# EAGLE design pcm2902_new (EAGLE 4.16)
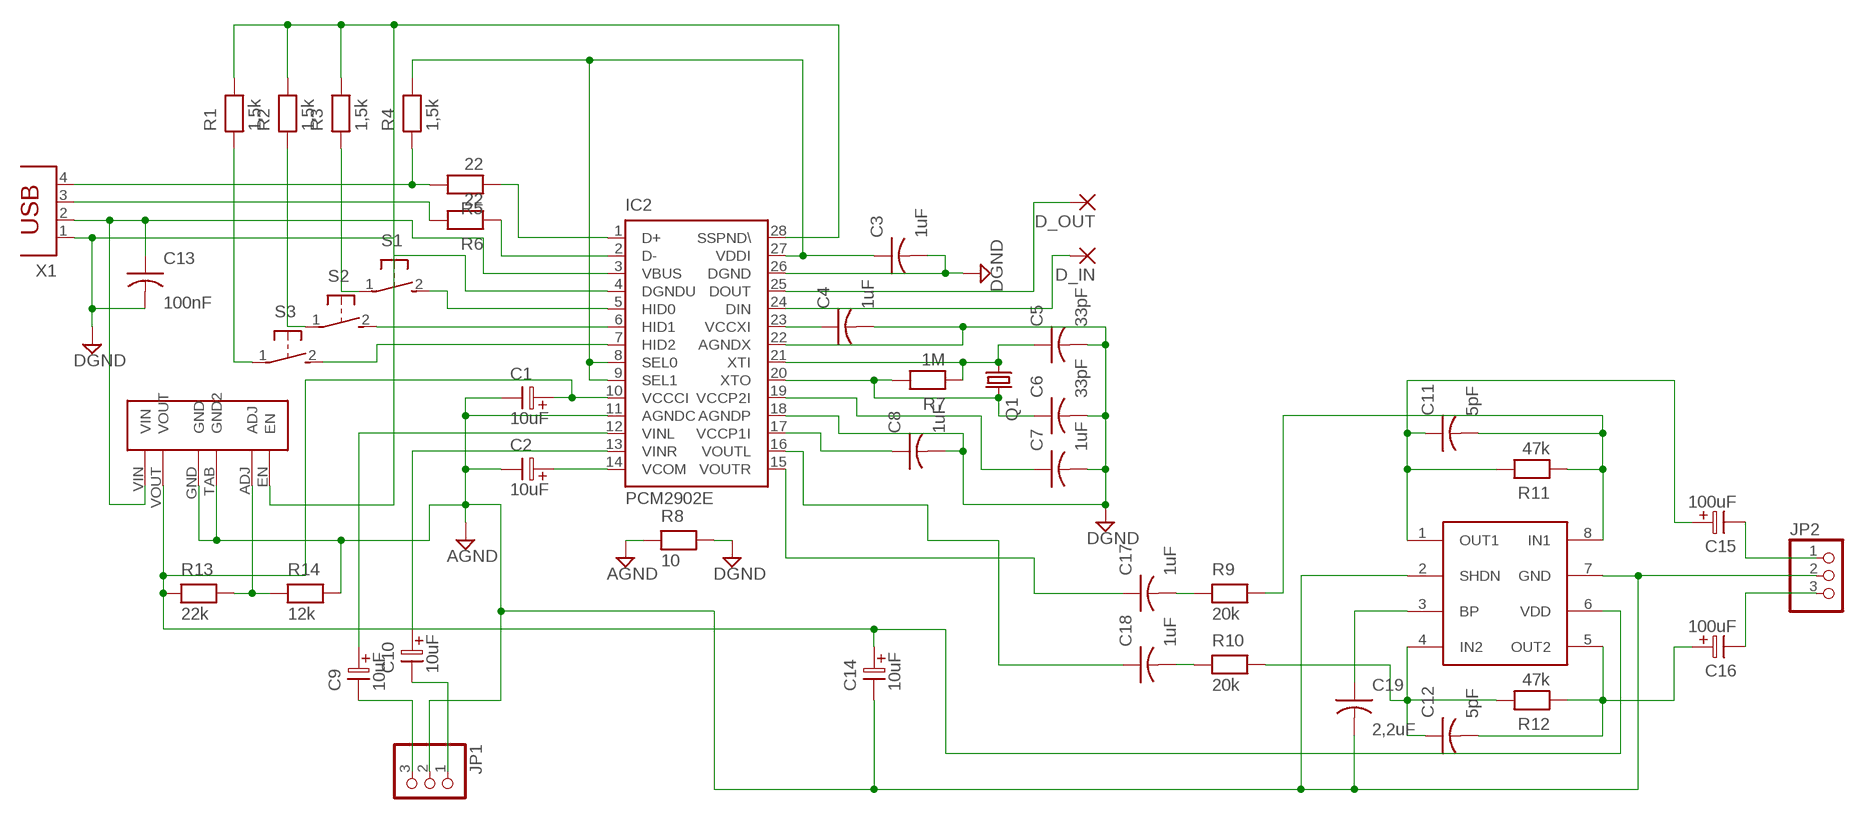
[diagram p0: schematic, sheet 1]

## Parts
C1  10uF  ELC-2,5L  [ES-2,5L]
C2  10uF  ELC-2,5L  [ES-2,5L]
C3  1uF  CAP-5  [C-5]
C4  1uF  CAP-5  [C-5]
C5  33pF  CAP-5  [C-5]
C6  33pF  CAP-5  [C-5]
C7  1uF  CAP-5  [C-5]
C8  1uF  CAP-5  [C-5]
C9  10uF  ELC-2,5L  [ES-2,5L]
C10  10uF  ELC-2,5L  [ES-2,5L]
C11  5pF  CAP-5  [C-5]
C12  5pF  CAP-5  [C-5]
C13  100nF  CAP-2,5  [C-2,5]
C14  10uF  ELC-2,5L  [ES-2,5L]
C15  100uF  ELC-2,5L  [ES-2,5L]
C16  100uF  ELC-2,5L  [ES-2,5L]
C17  1uF  CAP-5  [C-5]
C18  1uF  CAP-5  [C-5]
C19  2,2uF  CAP-5  [C-5]
D_IN  1,6/0,8  [1,6/0,8]
D_OUT  1,6/0,8  [1,6/0,8]
IC2  PCM2902E  [SSOP28DB]
JP1  PINHD-1X3  [1X03]
JP2  PINHD-1X3  [1X03]
Q1  CRYTALHC49S  [HC49/S]
R1  1,5k  RESEU-5  [R-5]
R2  1,5k  RESEU-5  [R-5]
R3  1,5k  RESEU-5  [R-5]
R4  1,5k  RESEU-5  [R-5]
R5  22  RESEU-5  [R-5]
R6  22  RESEU-5  [R-5]
R7  1M  RESEU-5  [R-5]
R8  10  RESEU-5  [R-5]
R9  20k  RESEU-5  [R-5]
R10  20k  RESEU-5  [R-5]
R11  47k  RESEU-5  [R-5]
R12  47k  RESEU-5  [R-5]
R13  22k  RESEU-5  [R-5]
R14  12k  RESEU-5  [R-5]
S1  31-XX  [B3F-31XX]
S2  31-XX  [B3F-31XX]
S3  31-XX  [B3F-31XX]
U$1  TPA302  [SOP8]
U$2  REG102GA-A  [SOT223-5]
X1  PN87520  [PN87520]

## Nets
AGND: C1.2 C2.2 C14.2 C19.2 IC2.11(AGNDC) JP1.2 JP2.2 R8.1 R14.2 U$1.2(SHDN) U$1.7(GND) U$2.GND U$2.TAB(GND2)
DGND: C3.2 C4.2 C5.2 C6.2 C7.2 C8.2 C13.2 IC2.4(DGNDU) IC2.18(AGNDP) IC2.22(AGNDX) IC2.26(DGND) R8.2 X1.1
N$1: C2.1 IC2.14(VCOM)
N$2: C1.1 C14.1 IC2.10(VCCCI) R13.1 U$1.6(VDD) U$2.VOUT
N$3: IC2.1(D+) R5.1
N$4: R4.1 R5.2 X1.4
N$5: R6.2 X1.3
N$6: IC2.2(D-) R6.1
N$7: IC2.6(HID1) S2.2(S)
N$8: C3.1 IC2.8(SEL0) IC2.9(SEL1) IC2.27(VDDI) R4.2
N$9: IC2.7(HID2) S3.2(S)
N$10: IC2.5(HID0) S1.2(S)
N$11: R1.1 S3.1(P)
N$12: R2.1 S2.1(P)
N$13: R3.1 S1.1(P)
N$14: C4.1 IC2.23(VCCXI)
N$15: IC2.28(SSPND\) R1.2 R2.2 R3.2 U$2.EN
N$16: C9.1 IC2.12(VINL)
N$17: C10.1 IC2.13(VINR)
N$18: C5.1 IC2.21(XTI) Q1.1 R7.1
N$19: C6.1 IC2.20(XTO) Q1.2 R7.2
N$20: C7.1 IC2.19(VCCP2I)
N$21: C8.1 IC2.17(VCCP1I)
N$22: D_OUT.1(P) IC2.25(DOUT)
N$23: D_IN.1(P) IC2.24(DIN)
N$24: C18.1 IC2.16(VOUTL)
N$25: C17.1 IC2.15(VOUTR)
N$26: R13.2 R14.1 U$2.ADJ
N$27: C9.2 JP1.3
N$28: C10.2 JP1.1
N$29: C19.1 U$1.3(BP)
N$30: C13.1 IC2.3(VBUS) U$2.VIN X1.2
N$32: C17.2 R9.1
N$33: C18.2 R10.1
N$34: C12.2 C16.1 R12.1 U$1.5(OUT2)
N$35: C12.1 R10.2 R12.2 U$1.4(IN2)
N$36: C11.1 C15.1 R11.2 U$1.1(OUT1)
N$37: C11.2 R9.2 R11.1 U$1.8(IN1)
N$39: C15.2 JP2.1
N$40: C16.2 JP2.3

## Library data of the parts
C1 C2 C9 C10 C14-C16 = discrete:ELC-2,5L
C3-C8 C11 C12 C17-C19 = discrete:CAP-5
C13 = discrete:CAP-2,5
D_IN D_OUT = wirepad:1,6/0,8: THROUGH-HOLE PAD
IC2 = texas:PCM290*: STEREO AUDIO CODEC WITH USB INTERFACE SINGLE-ENDED ANALOG INPUT/OUTPUT AND S/PDIF
JP1 JP2 = pinhead:PINHD-1X3: PIN HEADER
Q1 = crystal:CRYTAL: CRYSTAL
R1-R14 = discrete:RESEU-5
S1-S3 = switch-omron:31-XX: OMRON SWITCH
U$1 = tpa302:TPA302
U$2 = Reg102:REG102GA-A
X1 = con-berg:PN87520: BERG USB connector

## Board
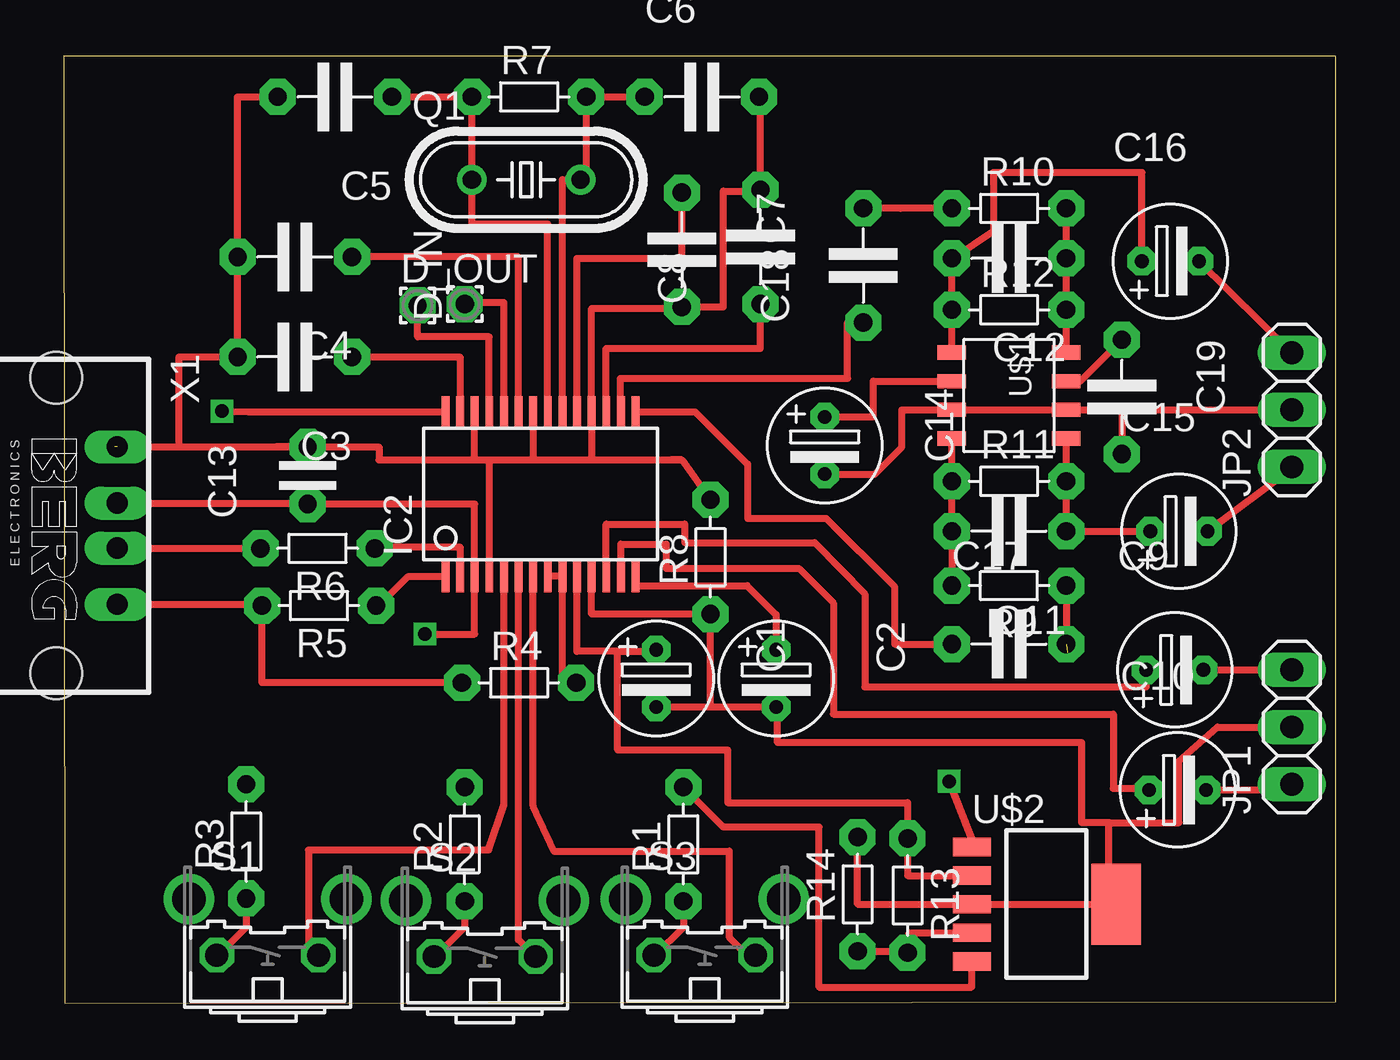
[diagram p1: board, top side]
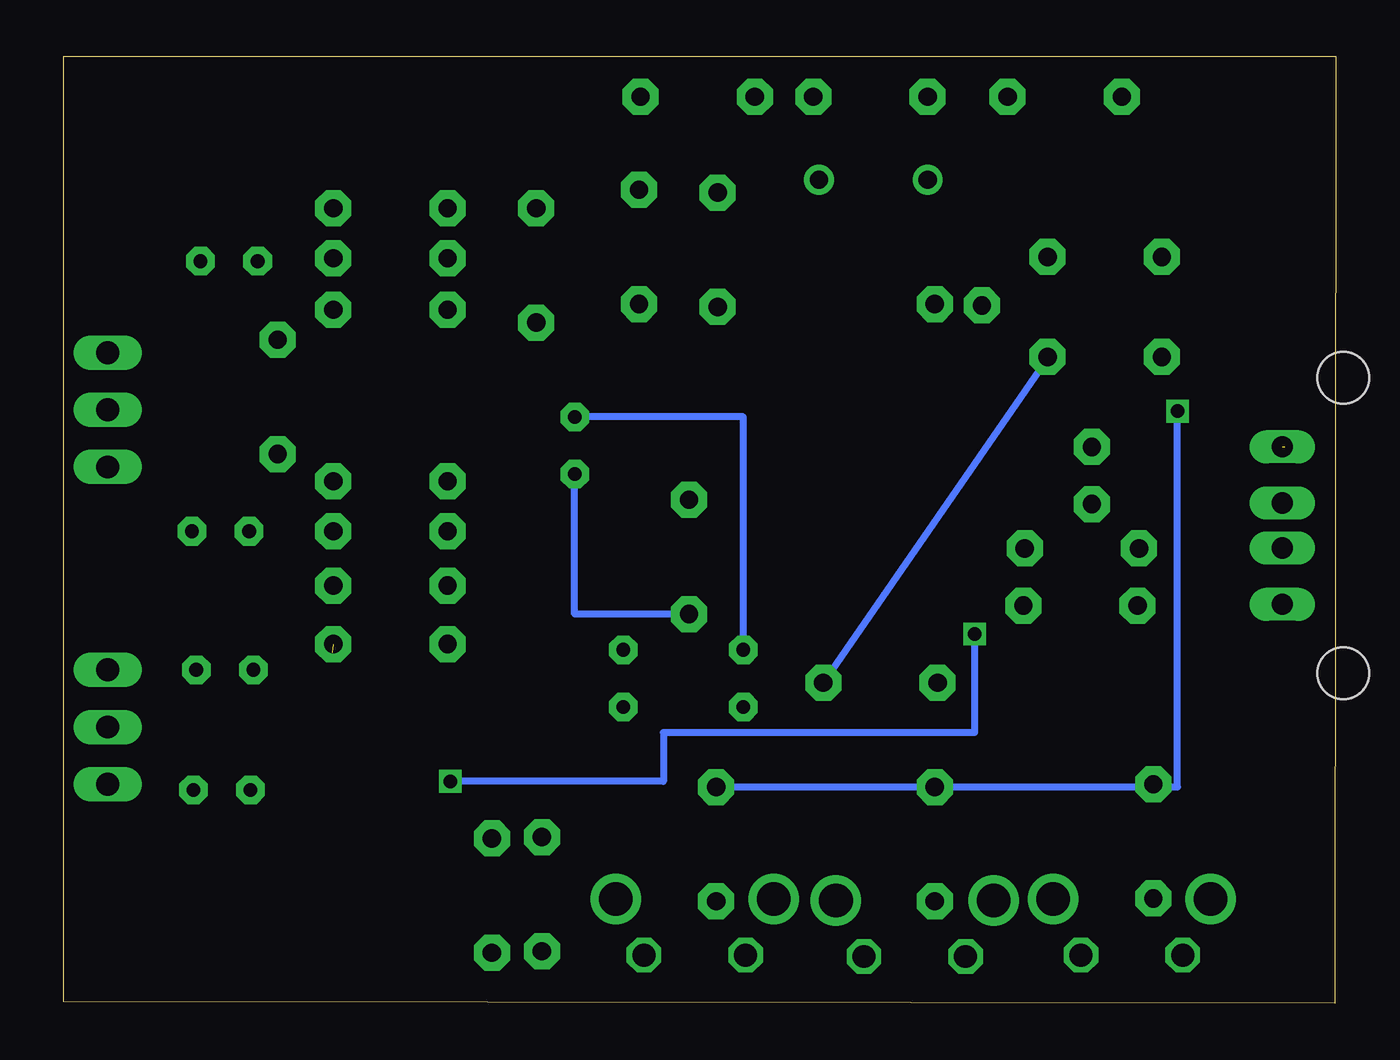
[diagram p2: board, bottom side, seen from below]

Size 56.56 x 42.09 mm. Coordinates in mm from the lower left corner, seen from the top.
Outline: 0.06,0 56.56,0.06 56.56,42.09 0,42.09 0.06,0
Copper layers (1*16): Top 0.035mm / dielectric 1.5mm / Bottom 0.035mm
Design rules "default": minimum track width 10mil, minimum drill 24mil, track to track 8mil, track to pad 8mil, pad to pad 8mil, via to via 8mil, smd to smd 8mil, copper to edge 40mil, drill to drill 8mil, minimum pad ring 10mil, minimum via ring 8mil, stop-mask expansion 4mil, vias tented up to drill 0mil, thermal gap 10mil

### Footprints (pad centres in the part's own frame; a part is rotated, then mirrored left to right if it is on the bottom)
ES-2,5L = drill 0.61 pad 1.27 octagon: 1 0,0; 2 2.54,0
C-5 = drill 0.813 pad 1.6 octagon: 1 -2.54,0; 2 2.54,0
C-2,5 = drill 0.813 pad 1.6 octagon: 1 -1.27,0; 2 1.27,0
1,6/0,8 = drill 0.813 pad 1.6 octagon: 1 0,0
SSOP28DB = smd 0.348 x 1.397: 1 -4.225,-3.656; 2 -3.575,-3.656; 3 -2.925,-3.656; 4 -2.275,-3.656; 5 -1.625,-3.656; 6 -0.975,-3.656; 7 -0.325,-3.656; 8 0.325,-3.656; 9 0.975,-3.656; 10 1.625,-3.656; 11 2.275,-3.656; 12 2.925,-3.656; 13 3.575,-3.656; 14 4.225,-3.656; 15 4.225,3.656; 16 3.575,3.656; 17 2.925,3.656; 18 2.275,3.656; 19 1.625,3.656; 20 0.975,3.656; 21 0.325,3.656; 22 -0.325,3.656; 23 -0.975,3.656; 24 -1.625,3.656; 25 -2.275,3.656; 26 -2.925,3.656; 27 -3.575,3.656; 28 -4.225,3.656
1X03 = drill 1.016 long: 1 -2.54,0; 2 0,0; 3 2.54,0
HC49/S = drill 0.813 round: 1 -2.413,0; 2 2.413,0
R-5 = drill 0.813 pad 1.6 octagon: 1 -2.54,0; 2 2.54,0
B3F-31XX = drill 1.016 octagon: 1 -2.261,-1.245; 2 2.261,-1.245 | drill 1.499 pad 2.159 round: 3 -3.505,1.245; 4 3.505,1.245
SOP8 = smd 0.635 x 1.27: 1 -1.905,-2.54; 2 -0.635,-2.54; 3 0.635,-2.54; 4 1.905,-2.54; 5 1.905,2.54; 6 0.635,2.54; 7 -0.635,2.54; 8 -1.905,2.54
SOT223-5 = smd 0.813 x 1.676: ADJ 1.27,-3.302; EN 2.54,-3.302; GND 0,-3.302; VIN -2.54,-3.302; VOUT -1.27,-3.302 | smd 3.6 x 2.2: TAB 0,3.099
PN87520 = drill 0.95 long: 1 -3.5,2.71; 2 -1,2.71; 3 1,2.71; 4 3.5,2.71 | hole 2.3: -6.57,0; 6.57,0

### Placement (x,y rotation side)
C1  26.35,15.71 270 top
C2  31.68,15.71 270 top
C3  10.28,28.73 180 top
C4  10.28,33.17 180 top
C5  12.06,40.28 180 top
C6  28.38,40.28 0 top
C7  27.49,33.49 270 top
C8  30.98,33.62 90 top
C9  48.13,14.82 0 top
C10  48.25,9.49 0 top
C11  42.03,20.98 180 top
C12  42.03,33.11 180 top
C13  10.85,23.46 90 top
C14  33.84,26.06 270 top
C15  48.32,20.98 0 top
C16  47.94,32.98 0 top
C17  42.03,15.96 0 top
C18  35.56,32.79 90 top
C19  47.05,26.95 270 top
D_IN  17.84,31.08 90 top
D_OUT  15.74,31.01 0 top
IC2  21.2,22.63 0 top
JP1  54.61,12.28 90 top
JP2  54.61,26.38 90 top
Q1  20.57,36.6 0 top
R1  27.55,7.07 90 top
R2  17.84,7.07 90 top
R3  8.12,7.2 90 top
R4  20.25,14.25 0 top
R5  11.36,17.68 180 top
R6  11.3,20.22 180 top
R7  20.7,40.28 0 top
R8  28.76,19.84 90 top
R9  42.03,18.57 180 top
R10  42.03,35.33 0 top
R11  42.03,23.2 0 top
R12  42.03,30.82 0 top
R13  37.52,4.79 270 top
R14  35.3,4.85 90 top
S1  9.08,3.39 0 top
S2  18.73,3.33 0 top
S3  28.51,3.39 0 top
U$1  42.03,27.01 90 top
U$2  43.68,4.41 270 top
X1  -0.32,21.23 270 top

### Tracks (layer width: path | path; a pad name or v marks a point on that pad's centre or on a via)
AGND
  Top 0.305: 28.76,13.17 C1.2 | 28.76,13.17 C2.2 31.75,13.17 31.75,11.58 45.27,11.58 45.27,8.03 46.48,8.03 | IC2.11 23.48,17.3 R8.1 28.76,17.11 | 28.76,13.17 28.76,17.11 | 28.76,17.11 28.7,17.11 | JP1.2 51.3,12.28 49.59,10.76 49.59,8.03 46.48,8.03 | 47.05,26.38 U$1.2 U$1.7 37.27,26.38 37.27,24.71 36.08,23.52 C14.2 | 47.05,26.38 C19.2 | 47.05,26.38 JP2.2 | 46.8,4.41 U$2.TAB 46.48,4.41 | 40.57,4.41 46.48,4.41 | 46.48,4.41 46.48,8.03 | 40.57,4.41 U$2.GND | R14.2 35.3,4.41 40.57,4.41
  Bottom 0.305: 28.63,17.3 R8.1 33.84,17.3 C14.2
DGND  (1 unrouted)
  Top 0.305: 20.89,26.28 IC2.22 20.89,26.29 20.89,24.16 | 27.49,24.16 R8.2 | 18.28,24.16 14.03,24.16 14.03,24.73 C13.2 | 18.28,24.16 18.92,24.16 | 18.92,24.16 20.89,24.16 | 20.89,24.16 23.49,24.16 | 23.49,24.16 27.49,24.16 | 27.49,24.16 26.98,24.16 | 2.28,24.73 5.14,24.73 | 5.14,24.73 C13.2 | IC2.26 18.28,24.16 | 23.49,24.16 23.49,26.29 IC2.18 23.48,30.89 27.49,30.89 C7.2 29.33,30.95 29.33,36.09 30.86,36.09 C8.2 30.98,40.09 C6.2 | 5.14,24.73 5.14,28.73 C3.2 C4.2 7.74,40.28 C5.2 | C13.2 9.46,24.73 | IC2.4 18.93,19 18.92,19.01 18.92,24.16
N$1
  Top 0.305: 25.46,19.01 25.46,18.98 IC2.14 25.43,18.57 30.39,18.57 31.68,17.27 C2.1
N$2
  Top 0.305: C1.1 26.35,15.65 24.63,15.65 | IC2.10 22.83,15.65 24.63,15.65 | U$1.6 36,27.65 36,26.06 33.78,26.06 | C14.1 33.78,26.06 | 33.78,26.06 33.78,26.12 | U$2.VOUT 37.52,5.68 R13.1 37.52,8.92 29.52,8.92 29.52,11.26 24.63,11.26 24.63,15.65
  Bottom 0.305: 33.9,26.06 C14.1 26.35,26.06 C1.1
N$3
  Top 0.305: R5.1 13.96,17.62 15.33,18.98 IC2.1
N$4
  Top 0.305: R5.2 8.89,17.68 8.83,17.73 X1.4 | R5.2 8.82,17.74 | R4.1 8.82,14.25 R5.2
N$5
  Top 0.305: X1.3 8.74,20.23 R6.2
N$6
  Top 0.305: 13.84,20.28 13.77,20.28 | R6.1 13.84,20.28 | IC2.2 17.63,20.28 13.84,20.28
N$7
  Top 0.305: S2.2 20.99,2.06 20.23,2.82 IC2.6
N$8
  Top 0.305: 21.53,18.96 21.52,18.95 | 21.53,18.96 IC2.8 | 21.53,18.96 21.55,18.98 IC2.9 22.18,14.25 R4.2 | IC2.27 17.63,28.73 C3.1 12.76,28.73 12.76,28.79
  Bottom 0.305: R4.2 12.76,28.73
N$9
  Top 0.305: 30.79,2.12 S3.2 30.77,2.12 30.79,2.12 | IC2.7 20.88,8.77 21.81,6.76 28.51,6.76 29.59,6.77 29.59,2.95 30.41,2.12 30.79,2.12
N$10
  Top 0.305: IC2.5 19.58,8.83 18.91,6.82 10.89,6.82 10.92,6.78 10.92,2.67 11.34,2.25 | 11.34,2.25 11.36,2.25 | S1.2 11.34,2.25
N$11
  Top 0.305: S3.1 26.26,2.15 26.28,2.12 27.55,3.39 R1.1
N$12
  Top 0.305: S2.1 16.47,1.97 16.5,2.06 17.84,3.39 R2.1
N$13
  Top 0.305: S1.1 6.83,2.15 6.85,2.12 8.12,3.39 R3.1
N$14
  Top 0.305: IC2.23 20.23,33.17 C4.1
N$15  (via drill 0.6)
  Top 0.305: IC2.28 8.22,26.29 v7.04,26.31 | U$2.EN 40.38,0.72 33.59,0.72 33.59,7.84 29.33,7.84 R1.2
  Bottom 0.305: 8.31,9.61 R3.2 8.12,9.61 | 8.12,9.61 7.04,9.61 v7.04,26.31 | 8.12,9.61 8.31,9.61 | 8.31,9.61 R2.2 R1.2
N$16
  Top 0.305: IC2.12 24.13,21.3 27.62,21.3 27.62,20.47 33.4,20.47 35.62,18.19 35.62,14.06 48.13,14.06 C9.1 48.19,14.82
N$17
  Top 0.305: IC2.13 24.78,20.41 26.79,20.41 26.79,19.33 32.69,19.33 34.22,17.8 34.22,12.85 46.67,12.85 46.67,9.55 48.25,9.55 C10.1
N$18
  Top 0.305: C5.1 R7.1 Q1.1 18.16,34.63 21.53,34.63 IC2.21
N$19
  Top 0.305: C6.1 R7.2 23.24,36.6 22.92,36.6 | IC2.20 22.18,36.6 22.92,36.6 | 22.92,36.6 Q1.2
N$20
  Top 0.305: IC2.19 22.83,33.11 27.49,33.11 C7.1
N$21
  Top 0.305: IC2.17 24.13,29.11 30.98,29.11 C8.1 30.98,31.01
N$22
  Top 0.305: IC2.25 18.93,29.62 15.74,29.62 D_OUT.1
N$23
  Top 0.305: 17.78,31.14 17.84,31.14 | 17.84,31.14 D_IN.1 | IC2.24 19.58,31.14 17.84,31.14
N$24
  Top 0.305: IC2.16 24.76,26.29 24.76,27.77 34.86,27.77 34.86,30.25 C18.1
N$25
  Top 0.305: C17.1 36.95,15.96 36.95,18.5 33.9,21.55 30.41,21.55 30.41,23.96 28.08,26.29 IC2.15
N$26
  Top 0.305: U$2.ADJ 37.59,3.14 37.59,2.31 | 37.59,2.31 37.59,2.25 R13.2 | R14.1 37.59,2.31
N$27
  Top 0.305: 54.73,14.82 JP1.3 C9.2
N$28
  Top 0.305: 54.67,9.8 JP1.1 54.35,9.49 C10.2
N$29
  Top 0.305: U$1.3 45.21,27.65 C19.1
N$30  (via drill 0.6)
  Top 0.305: X1.2 10.85,22.23 C13.1 18.28,22.19 IC2.3 18.28,16.41 v16.06,16.41 | U$2.VIN 40.51,6.95 v39.36,9.87
  Bottom 0.305: v39.36,9.87 29.9,9.87 29.9,12.03 16.06,12.03 v16.06,16.41
N$32  (1 unrouted)
  Top 0.305: R9.1 C17.2
N$33
  Top 0.305: 37.21,35.33 C18.2 R10.1
N$34
  Top 0.305: U$1.5 R12.1 C12.2 39.56,33.11 41.33,34.32 41.33,36.92 47.94,36.92 C16.1
N$35
  Top 0.305: U$1.4 R12.2 C12.1 R10.2
N$36
  Top 0.305: R11.2 44.57,23.14 | R11.2 U$1.1 | C11.1 44.57,20.92 | C11.1 R11.2 | C11.1 C15.1
N$37
  Top 0.305: R11.1 39.49,23.14 | R11.1 U$1.8 | R11.1 C11.2 R9.2
N$39
  Top 0.305: JP2.1 54.61,23.77 C15.2
N$40
  Top 0.305: JP2.3 C16.2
